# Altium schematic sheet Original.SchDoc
size A3
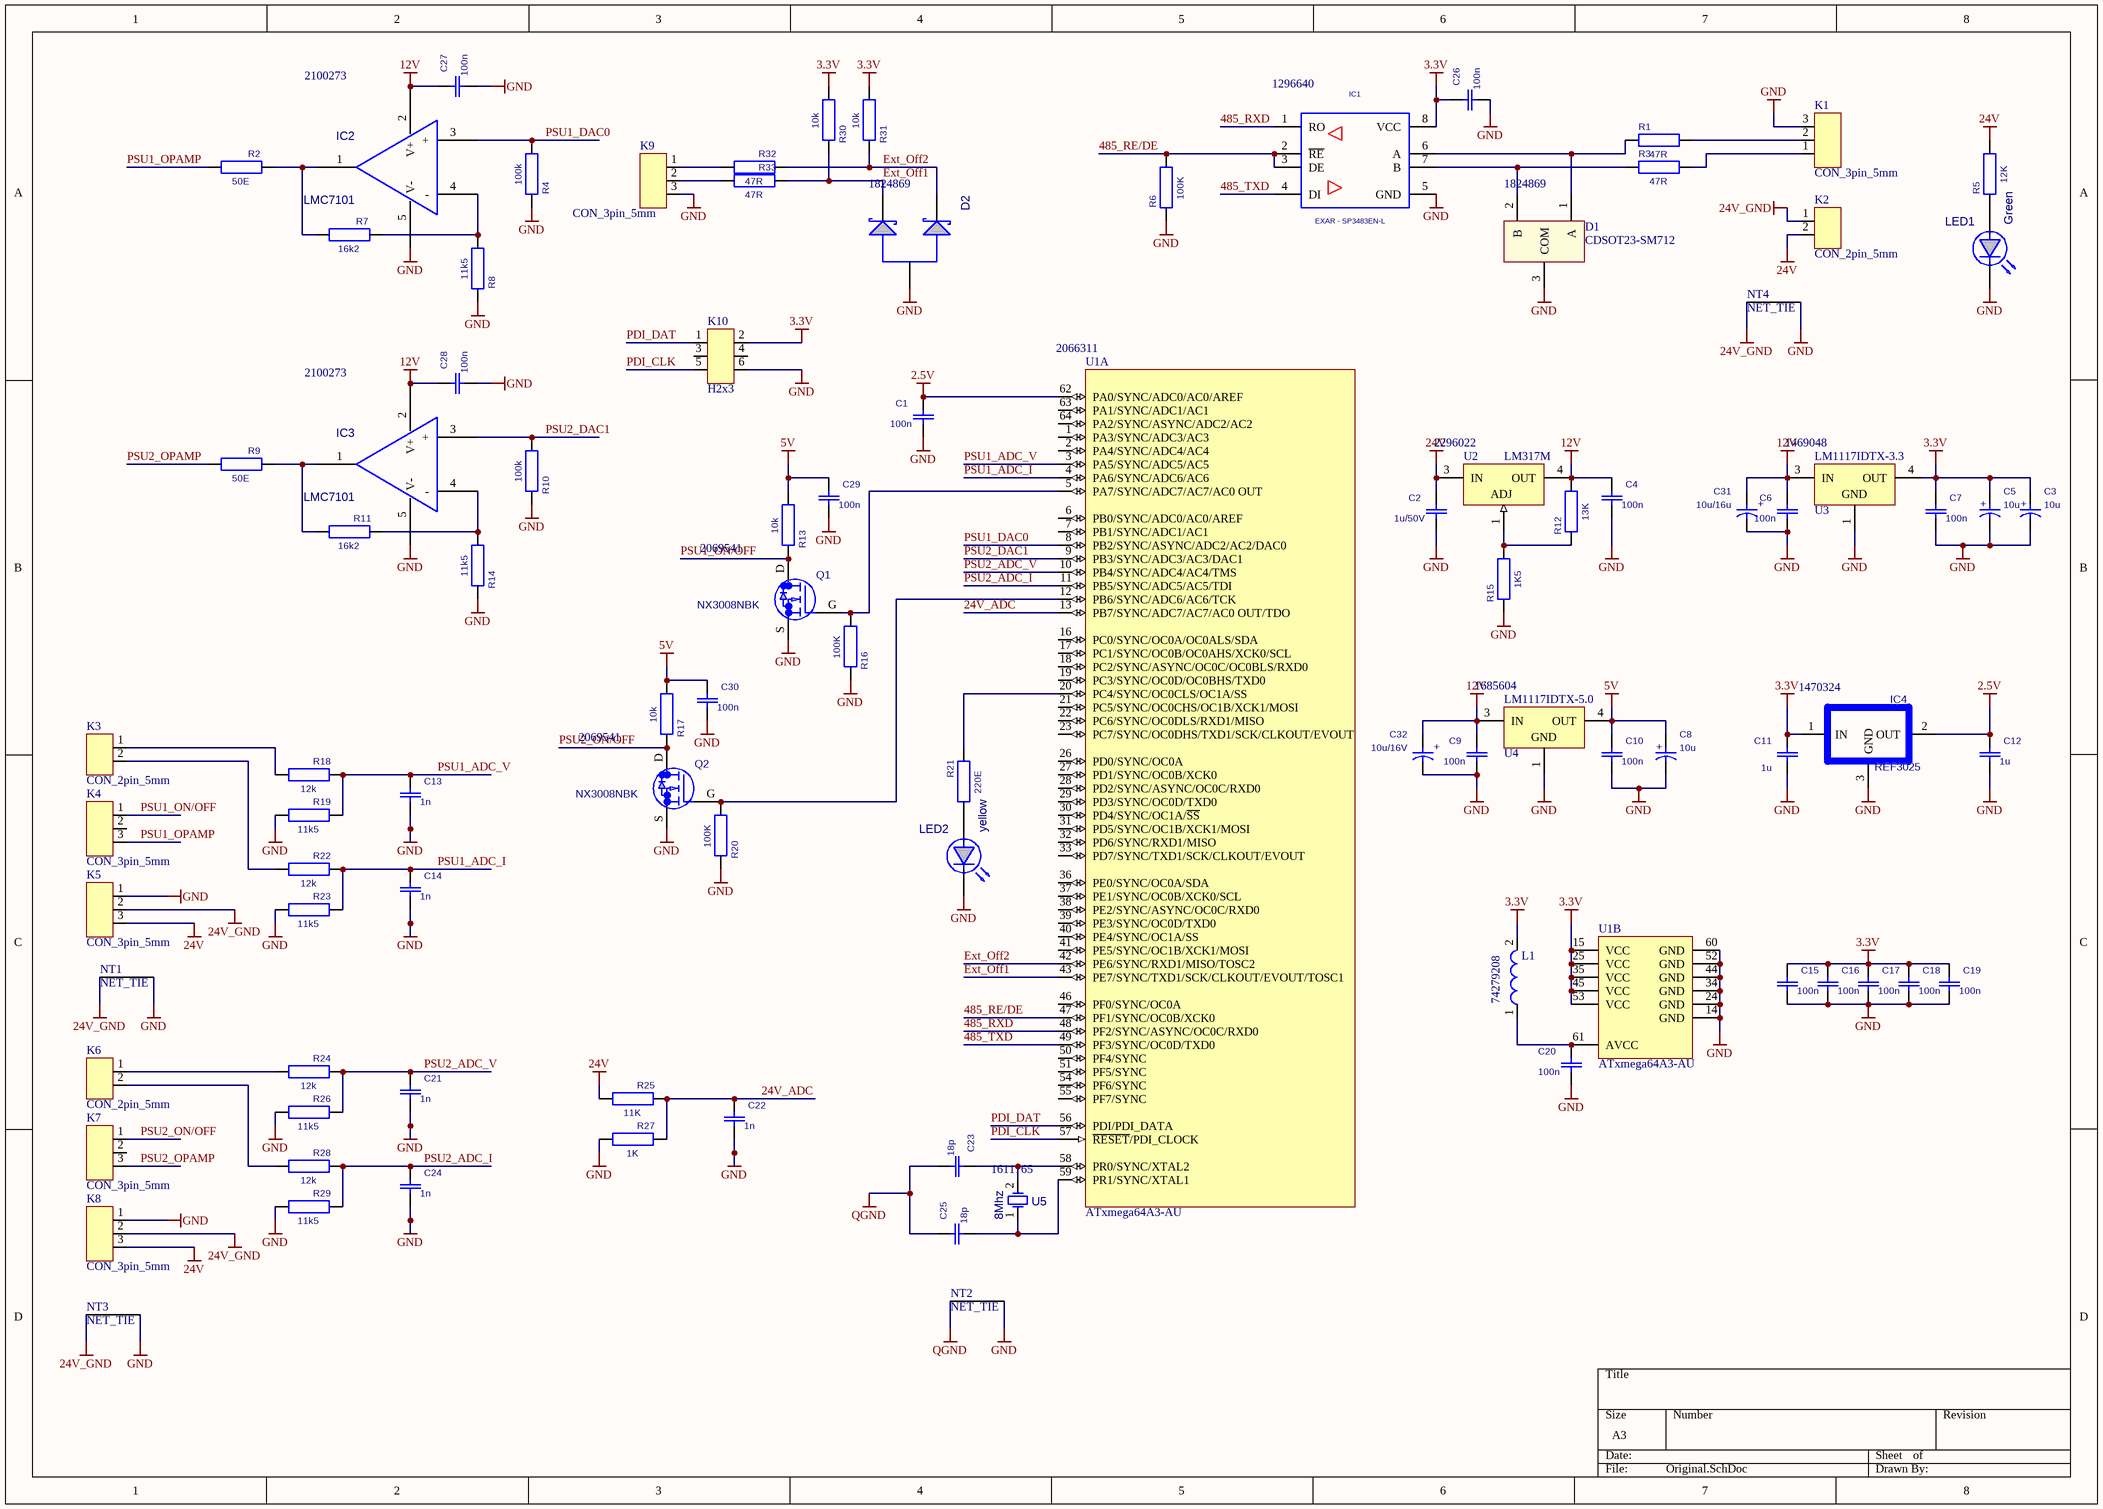
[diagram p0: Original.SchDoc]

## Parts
C1  100n  [C0805]
C2  1u/50V  [C0805]
C3  10u  [CT_A]
C4  100n  [C0805]
C5  10u  [CT_A]
C6  100n  [C0805]
C7  100n  [C0805]
C8  10u  [CT_A]
C9  100n  [C0805]
C10  100n  [C0805]
C11  1u  [C0805]
C12  1u  [C0805]
C13  1n  [C0805]
C14  1n  [C0805]
C15  100n  [C0805]
C16  100n  [C0805]
C17  100n  [C0805]
C18  100n  [C0805]
C19  100n  [C0805]
C20  100n  [C0805]
C21  1n  [C0805]
C22  1n  [C0805]
C23  18p  [C0805]
C24  1n  [C0805]
C25  18p  [C0805]
C26  100n  [C0805]
C27  100n  [C0805]
C28  100n  [C0805]
C29  100n  [C0805]
C30  100n  [C0805]
C31  10u/16u  [CT_A]
C32  10u/16V  [CT_A]
D1  CDSOT23-SM712  Supplier Part Number 2: 1824869  [SOT23(BAT54)]
D2  Supplier Part Number 1: 1824869  [SOT-663]  (hidden comment: CDSOT23-SM712)
IC1  EXAR - SP3483EN-L  Supplier Part Number 1: 1296640  [SO8R]
IC2  LMC7101  Supplier Part Number 1: 2100273  [SO-G5/P.95]
IC3  LMC7101  Supplier Part Number 1: 2100273  [SO-G5/P.95]
IC4  REF3025  Supplier Part Number 1: 1470324  [SOT23]
K1  CON_3pin_5mm  [COM_3pin_5mm]
K2  CON_2pin_5mm  [CON_2pin_5mm]
K3  CON_2pin_5mm  [CON_2pin_5mm]
K4  CON_3pin_5mm  [COM_3pin_5mm]
K5  CON_3pin_5mm  [COM_3pin_5mm]
K6  CON_2pin_5mm  [CON_2pin_5mm]
K7  CON_3pin_5mm  [COM_3pin_5mm]
K8  CON_3pin_5mm  [COM_3pin_5mm]
K9  CON_3pin_5mm  [COM_3pin_5mm]
K10  H2x3  [H2x3]
L1  74279208  [SMD-0805]
LED1  value Green  [LED0805]  (hidden comment: LED0805)
LED2  value yellow  [LED0805]  (hidden comment: LED0805)
NT1  NET_TIE  [NET_TIE_LINE]  (net tie, no BOM)
NT2  NET_TIE  [NET_TIE_LINE]  (net tie, no BOM)
NT3  NET_TIE  [NET_TIE_LINE]  (net tie, no BOM)
NT4  NET_TIE  [NET_TIE_LINE]  (net tie, no BOM)
Q1  NX3008NBK  Supplier Part Number 1: 2069541  [SOT23(IRLML2502)]
Q2  NX3008NBK  Supplier Part Number 1: 2069541  [SOT23(IRLML2502)]
R1  47R  [R0805]
R2  50E  [R0805]
R3  47R  [R0805]
R4  100k  [R0805]
R5  12K  [R0805]
R6  100K  [R0805]
R7  16k2  [R0805]
R8  11k5  [R0805]
R9  50E  [R0805]
R10  100k  [R0805]
R11  16k2  [R0805]
R12  13K  [R0805]
R13  10k  [R0805]
R14  11k5  [R0805]
R15  1K5  [R0805]
R16  100K  [R0805]
R17  10k  [R0805]
R18  12k  [R0805]
R19  11k5  [R0805]
R20  100K  [R0805]
R21  220E  [R0805]
R22  12k  [R0805]
R23  11k5  [R0805]
R24  12k  [R0805]
R25  11K  [R0805]
R26  11k5  [R0805]
R27  1K  [R0805]
R28  12k  [R0805]
R29  11k5  [R0805]
R30  10k  [R0805]
R31  10k  [R0805]
R32  47R  [R0805]
R33  47R  [R0805]
U1  ATxmega64A3-AU  Supplier Part Number 1: 2066311  [64A_M]  (parts A,B of 2)
U2  LM317M  Supplier Part Number 1: 2296022  [TD03B_M]
U3  LM1117IDTX-3.3  Supplier Part Number 1: 1469048  [TD03B_M]
U4  LM1117IDTX-5.0  Supplier Part Number 1: 1685604  [TD03B_M]
U5  8Mhz  Supplier Part Number 1: 1611765  [HC49/4H_SMX]

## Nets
2.5V: C1.1 C12.1 IC4.2(OUT) U1.62(PA0/SYNC/ADC0/AC0/AREF)
3.3V: C3.1 C5.1 C7.1 C11.1 C15.1 C16.1 C17.1 C18.1 C19.1 C26.1 IC1.8(VCC) IC4.1(IN) K10.2 L1.2 R30.2 R31.2 U1.15(VCC) U1.25(VCC) U1.35(VCC) U1.45(VCC) U1.53(VCC) U3.4(OUT)
5V: C8.1 C10.1 C29.1 C30.1 R13.2 R17.2 U4.4(OUT)
12V: C4.1 C6.1 C9.1 C27.1 C28.1 C31.1 C32.1 IC2.2(V+) IC3.2(V+) R12.2 U2.4(OUT) U3.3(IN) U4.3(IN)
24V: C2.1 K2.2 K5.3 K8.3 R5.2 R25.2 U2.3(IN)
24V_GND: K2.1 K5.2 K8.2 NT1.1 NT3.1 NT4.1
GND: C1.2 C2.2 C3.2 C4.2 C5.2 C6.2 C7.2 C8.2 C9.2 C10.2 C11.2 C12.2 C13.2 C14.2 C15.2 C16.2 C17.2 C18.2 C19.2 C20.2 C21.2 C22.2 C24.2 C26.2 C27.2 C28.2 C29.2 C30.2 C31.2 C32.2 D1.3(COM) D2.2(A2) IC1.5(GND) IC2.5(V-) IC3.5(V-) IC4.3(GND) K1.3 K5.1 K8.1 K9.3 K10.6 LED1.K LED2.K NT1.2 NT2.2 NT3.2 NT4.2 Q1.S Q2.S R4.1 R6.1 R8.1 R10.1 R14.1 R15.1 R16.1 R19.2 R20.1 R23.2 R26.2 R27.2 R29.2 U1.14(GND) U1.24(GND) U1.34(GND) U1.44(GND) U1.52(GND) U1.60(GND) U3.1(GND) U4.1(GND)
QGND: C23.2 C25.1 NT2.1
24V_ADC: C22.1 R25.1 R27.1 U1.13(PB7/SYNC/ADC7/AC7/AC0_OUT/TDO)
485_RE/DE: IC1.2(~{RE}) IC1.3(DE) R6.2 U1.47(PF1/SYNC/OC0B/XCK0)
485_RXD: IC1.1(RO) U1.48(PF2/SYNC/ASYNC/OC0C/RXD0)
485_TXD: IC1.4(DI) U1.49(PF3/SYNC/OC0D/TXD0)
Ext_Off1: D2.3(K) R30.1 R33.1 U1.43(PE7/SYNC/TXD1/SCK/CLKOUT/EVOUT/TOSC1)
Ext_Off2: D2.1(A1) R31.1 R32.1 U1.42(PE6/SYNC/RXD1/MISO/TOSC2)
PDI_CLK: K10.5 U1.57(~{RESET}/PDI_CLOCK)
PDI_DAT: K10.1 U1.56(PDI/PDI_DATA)
PSU1_ADC_I: C14.1 R22.1 R23.1 U1.4(PA6/SYNC/ADC6/AC6)
PSU1_ADC_V: C13.1 R18.1 R19.1 U1.3(PA5/SYNC/ADC5/AC5)
PSU1_DAC0: IC2.3(+) R4.2 U1.8(PB2/SYNC/ASYNC/ADC2/AC2/DAC0)
PSU1_ON/OFF: K4.1 Q1.D R13.1
PSU1_OPAMP: K4.3 R2.2
PSU2_ADC_I: C24.1 R28.1 R29.1 U1.11(PB5/SYNC/ADC5/AC5/TDI)
PSU2_ADC_V: C21.1 R24.1 R26.1 U1.10(PB4/SYNC/ADC4/AC4/TMS)
PSU2_DAC1: IC3.3(+) R10.2 U1.9(PB3/SYNC/ADC3/AC3/DAC1)
PSU2_ON/OFF: K7.1 Q2.D R17.1
PSU2_OPAMP: K7.3 R9.2
NetC20_1: C20.1 L1.1 U1.61(AVCC)
NetC23_1: C23.1 U1.58(PR0/SYNC/XTAL2) U5.2(OSC2)
NetC25_2: C25.2 U1.59(PR1/SYNC/XTAL1) U5.1(OSC1)
NetD1_1: D1.1(A) IC1.6(A) R1.1
NetD1_2: D1.2(B) IC1.7(B) R3.1
NetIC2_1: IC2.1 R2.1 R7.2
NetIC2_4: IC2.4(-) R7.1 R8.2
NetIC3_1: IC3.1 R9.1 R11.2
NetIC3_4: IC3.4(-) R11.1 R14.2
NetK1_1: K1.1 R3.2
NetK1_2: K1.2 R1.2
NetK3_1: K3.1 R18.2
NetK3_2: K3.2 R22.2
NetK6_1: K6.1 R24.2
NetK6_2: K6.2 R28.2
NetK9_1: K9.1 R32.2
NetK9_2: K9.2 R33.2
NetLED1_A: LED1.A R5.1
NetLED2_A: LED2.A R21.2
NetQ1_G: Q1.G R16.2 U1.5(PA7/SYNC/ADC7/AC7/AC0_OUT)
NetQ2_G: Q2.G R20.2 U1.12(PB6/SYNC/ADC6/AC6/TCK)
NetR12_1: R12.1 R15.2 U2.1(ADJ)
NetR21_1: R21.1 U1.20(PC4/SYNC/OC0CLS/OC1A/SS)

Not connected (* = marked no-connect by the designer): K4 2; K7 2; K10 3 4; U1 1(PA3/SYNC/ADC3/AC3) 2(PA4/SYNC/ADC4/AC4) 6(PB0/SYNC/ADC0/AC0/AREF) 7(PB1/SYNC/ADC1/AC1) 16(PC0/SYNC/OC0A/OC0ALS/SDA) 17(PC1/SYNC/OC0B/OC0AHS/XCK0/SCL) 18(PC2/SYNC/ASYNC/OC0C/OC0BLS/RXD0) 19(PC3/SYNC/OC0D/OC0BHS/TXD0) 21(PC5/SYNC/OC0CHS/OC1B/XCK1/MOSI) 22(PC6/SYNC/OC0DLS/RXD1/MISO) 23(PC7/SYNC/OC0DHS/TXD1/SCK/CLKOUT/EVOUT) 26(PD0/SYNC/OC0A) 27(PD1/SYNC/OC0B/XCK0) 28(PD2/SYNC/ASYNC/OC0C/RXD0) 29(PD3/SYNC/OC0D/TXD0) 30(PD4/SYNC/OC1A/~{SS}) 31(PD5/SYNC/OC1B/XCK1/MOSI) 32(PD6/SYNC/RXD1/MISO) 33(PD7/SYNC/TXD1/SCK/CLKOUT/EVOUT) 36(PE0/SYNC/OC0A/SDA) 37(PE1/SYNC/OC0B/XCK0/SCL) 38(PE2/SYNC/ASYNC/OC0C/RXD0) 39(PE3/SYNC/OC0D/TXD0) 40(PE4/SYNC/OC1A/SS) 41(PE5/SYNC/OC1B/XCK1/MOSI) 46(PF0/SYNC/OC0A) 50(PF4/SYNC) 51(PF5/SYNC) 54(PF6/SYNC) 55(PF7/SYNC) 63(PA1/SYNC/ADC1/AC1) 64(PA2/SYNC/ASYNC/ADC2/AC2)

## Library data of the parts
C1 C2 C4 C6 C7 C9-C30 = SMD CAPACITOR: SMD Chip Capacitor; Tolerance: {Tolerance}
C3 C5 C8 C31 C32 = CT_A: {Description}; RefProducer: {RefProducer}; Geometry: {Geometry}; Tolerance: {Tolerance}; MinESR: {MinESR}; MaxESR: {MaxESR}; SolventProof: {SolventProof}; LifeTime: {LifeTime}; TempRange: {TempRange}; Reference: {Reference}; RefProducerCode: {RefProducerCode}; Z(-25deg)/Z(+20deg): {Z(-25deg)/Z(+20deg)}; MaxLeakageCurrent: {MaxLeakageCurrent}; MinRippleCurrent: {MinRippleCurrent}
D2 = BAT54A: pin to pad: 2>3 3>2; ComponentLink2DescA4: Datasheet; Note: Pin 2 is not connected and is not drawn; ComponentLink1DescBC: Manufacturer Link
IC1 = MAX485CSA_(SO8): Line-Powered RS-232 Transceiver Chip; OriginalName: DS1275S; Value: {Value}; ComponentField6: Pin number 6 is Not Connected (NC); ComponentField7: Published 13-Oct-2000
IC4 = REF3040
K1 K4 K5 K7-K9 = CON_3pin_5mm: Konektor za Bernic ohišja, 5 mm
K2 K3 K6 = CON_2pin_5mm: Konektor za  Bernic ohišja Serija 605, 5 mm raster
K10 = H2x3: Header 2x3 (male)
L1 = 74279208: SMD EMI Suppression Ferrite Bead WE-CBF, Z = 40 Ohm; Impedance: 40 Ohm
LED1 LED2 = LED0805: Chip LED diode
Q1 Q2 = IRLML2502: Value: {Value}
R1-R33 = SMD RESISTOR: Surface mount resistor; Power: {Power}
U1 = ATxmega64A3-AU: 8/16-bit AVR XMEGA A3 Microcontroller, 1.6-3.6V, 32MHz, 64KB + 4KB Flash, 2KB EEPROM, 4KB SRAM, 64-pin TQFP, Industrial Grade (-40°C to 85°C), Pb-Free
U2 = LM317MDT: 3-Terminal Adjustable Regulator, 3-pin TO-252; Manufacturer: National Semiconductor; PackageTopMarking: NSUZXYTT*LM317*MDT; PowerWise: N; CompType: LDO IC; High-Reliability: Y
U3 = LM1117IDTX-3.3: 800mA Low-Dropout Linear Regulator, 3-pin TO-252; Manufacturer: National Semiconductor; PackageTopMarking: NSUZXYTT*LM1117*IDT-3.3; PowerWise: N; CompType: LDO IC; High-Reliability: Y
U4 = LM1117IDTX-5.0: 800mA Low-Dropout Linear Regulator, 3-pin TO-252; Manufacturer: National Semiconductor; PackageTopMarking: NSUZXYTT*LM1117*IDT-5.0; PowerWise: N; CompType: LDO IC; High-Reliability: Y
U5 = Q HC49 SMD: Q SMD; ComponentLink2DescA4: Datasheet; Note: PCB layout complies with manufacturer's recommendation.; ComponentLink1DescBC: Manufacturer Link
